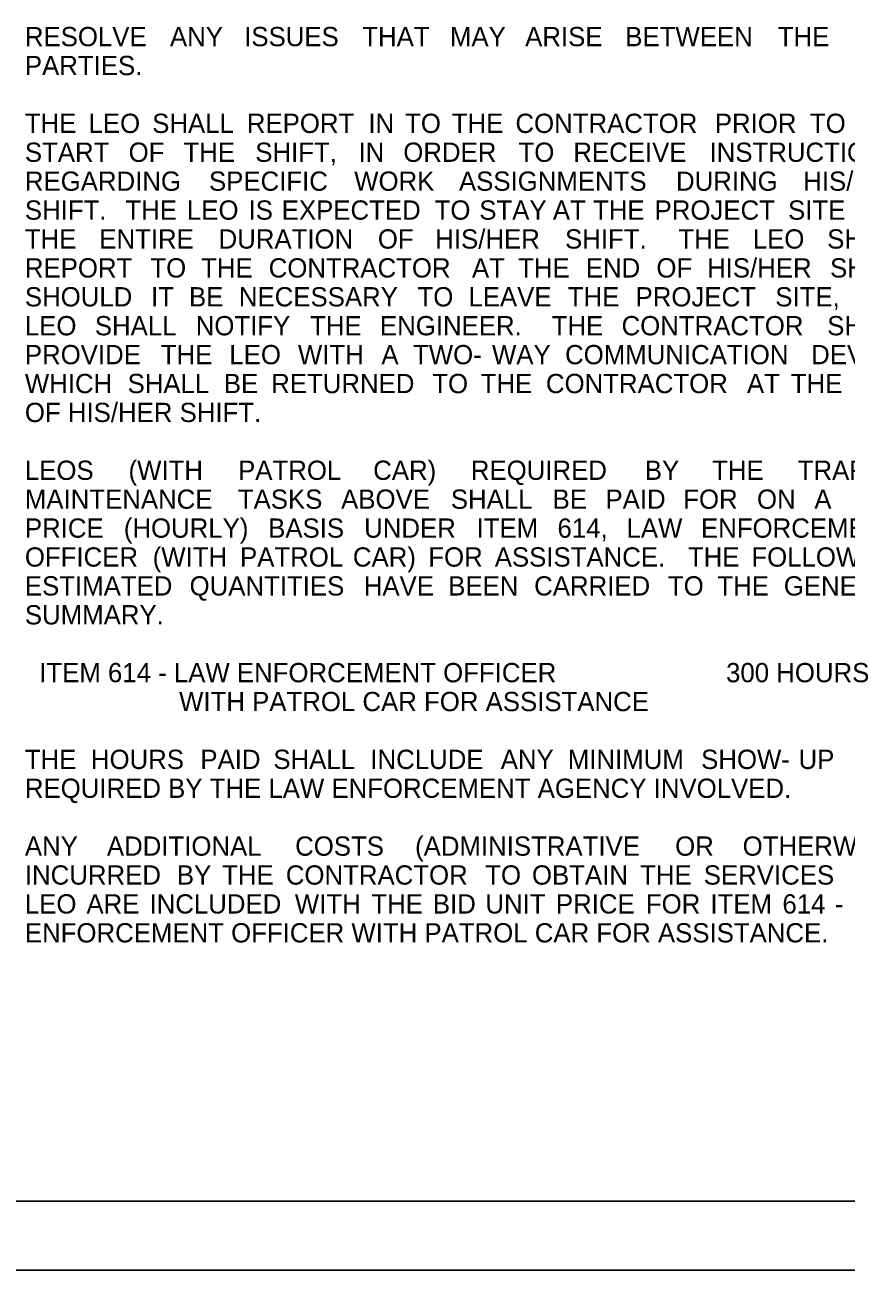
# Model space of a CAD drawing. Extents: x 0 to 34, y 0 to 22.
# Drawn here: x 24.66 to 30.62, y 0 to 9.04 of the extents above; entities that cross this region are included whole.
import ezdxf

# ---------------------------------------------------------------- set-up
doc = ezdxf.new("R2010")
doc.units = 0
for name, color, linetype in [('SH_Border', 7, 'Continuous'), ('SH_Cut_Line', 7, 'Continuous'), ('SH_Text', 7, 'Continuous')]:
    doc.layers.add(name, color=color, linetype=linetype)

msp = doc.modelspace()

# ---------------------------------------------------------------- linework, layer by layer
at = {"layer": 'SH_Border'}
msp.add_lwpolyline([(1.5, 21.5), (33.5, 21.5), (33.5, 0.5), (1.5, 0.5)], close=True, dxfattribs=at)
at = {"layer": 'SH_Cut_Line'}
msp.add_lwpolyline([(0, 0), (34, 0), (34, 22), (0, 22)], close=True, dxfattribs=at)

# ---------------------------------------------------------------- texts
at = {"layer": 'SH_Text'}
for s, p in [('RESOLVE ', (24.66, 8.89)), ('ANY ', (25.7136, 8.89)), ('ISSUES ', (26.2526, 8.89)), ('THAT ', (27.1103, 8.89)), ('MAY ', (27.7468, 8.89)), ('ARISE ', (28.2929, 8.89)), ('BETWEEN ', (29.0202, 8.89)), ('THE ', (30.1278, 8.89)), ('PARTIES.', (24.66, 8.68)), ('THE ', (24.66, 8.26)), ('LEO ', (25.1223, 8.26)), ('SHALL ', (25.5846, 8.26)), ('REPORT ', (26.2718, 8.26)), ('IN ', (27.1545, 8.26)), ('TO ', (27.4211, 8.26)), ('THE ', (27.7602, 8.26)), ('CONTRACTOR ', (28.2225, 8.26)), ('PRIOR ', (29.6702, 8.26)), ('TO ', (30.3607, 8.26)), ('START ', (24.66, 8.05)), ('OF ', (25.4134, 8.05)), ('THE ', (25.8116, 8.05)), ('SHIFT, ', (26.333, 8.05)), ('IN ', (27.0825, 8.05)), ('ORDER ', (27.4081, 8.05)), ('TO ', (28.2447, 8.05)), ('RECEIVE ', (28.643, 8.05)), ('INSTRUCTIONS ', (29.6319, 8.05)), ('REGARDING ', (24.66, 7.84)), ('SPECIFIC ', (25.997, 7.84)), ('WORK ', (27.0514, 7.84)), ('ASSIGNMENTS ', (27.8122, 7.84)), ('DURING ', (29.3885, 7.84)), ('HIS/HER ', (30.3123, 7.84)), ('SHIFT.  ', (24.66, 7.63)), ('THE ', (25.3897, 7.63)), ('LEO ', (25.837, 7.63)), ('IS ', (26.2843, 7.63)), ('EXPECTED ', (26.5251, 7.63)), ('TO ', (27.6357, 7.63)), ('STAY ', (27.9598, 7.63)), ('AT ', (28.4942, 7.63)), ('THE ', (28.7857, 7.63)), ('PROJECT ', (29.233, 7.63)), ('SITE ', (30.202, 7.63)), ('THE ', (24.66, 7.42)), ('ENTIRE ', (25.2004, 7.42)), ('DURATION ', (26.0668, 7.42)), ('OF ', (27.223, 7.42)), ('HIS/HER ', (27.6402, 7.42)), ('SHIFT.  ', (28.5828, 7.42)), ('THE ', (29.4056, 7.42)), ('LEO ', (29.946, 7.42)), ('SHALL ', (30.4864, 7.42)), ('REPORT ', (24.66, 7.21)), ('TO ', (25.5715, 7.21)), ('THE ', (25.9394, 7.21)), ('CONTRACTOR ', (26.4305, 7.21)), ('AT ', (27.9069, 7.21)), ('THE ', (28.2422, 7.21)), ('END ', (28.7333, 7.21)), ('OF ', (29.2461, 7.21)), ('HIS/HER ', (29.614, 7.21)), ('SHIFT. ', (30.5072, 7.21)), ('SHOULD ', (24.66, 7)), ('IT ', (25.5766, 7)), ('BE ', (25.8517, 7)), ('NECESSARY ', (26.2141, 7)), ('TO ', (27.5115, 7)), ('LEAVE ', (27.881, 7)), ('THE ', (28.6023, 7)), ('PROJECT ', (29.0949, 7)), ('SITE, ', (30.1094, 7)), ('LEO ', (24.66, 6.79)), ('SHALL ', (25.1679, 6.79)), ('NOTIFY ', (25.9006, 6.79)), ('THE ', (26.7308, 6.79)), ('ENGINEER.  ', (27.2386, 6.79)), ('THE ', (28.4855, 6.79)), ('CONTRACTOR ', (28.9932, 6.79)), ('SHALL ', (30.4864, 6.79)), ('PROVIDE ', (24.66, 6.58)), ('THE ', (25.647, 6.58)), ('LEO ', (26.1448, 6.58)), ('WITH ', (26.6427, 6.58)), ('A ', (27.2489, 6.58)), ('TWO-', (27.4787, 6.58)), ('WAY ', (28.0522, 6.58)), ('COMMUNICATION ', (28.5828, 6.58)), ('DEVICE ', (30.37, 6.58)), ('WHICH ', (24.66, 6.37)), ('SHALL ', (25.4057, 6.37)), ('BE ', (26.1048, 6.37)), ('RETURNED ', (26.4488, 6.37)), ('TO ', (27.6186, 6.37)), ('THE ', (27.9697, 6.37)), ('CONTRACTOR ', (28.4439, 6.37)), ('AT ', (29.9036, 6.37)), ('THE ', (30.222, 6.37)), ('OF HIS/HER SHIFT.', (24.66, 6.16)), ('LEOS ', (24.66, 5.74)), ('(WITH ', (25.4128, 5.74)), ('PATROL ', (26.2084, 5.74)), ('CAR) ', (27.1894, 5.74)), ('REQUIRED ', (27.8984, 5.74)), ('BY ', (29.1619, 5.74)), ('THE ', (29.6502, 5.74)), ('TRAFFIC ', (30.2724, 5.74)), ('MAINTENANCE ', (24.66, 5.53)), ('TASKS ', (26.2067, 5.53)), ('ABOVE ', (26.9564, 5.53)), ('SHALL ', (27.7533, 5.53)), ('BE ', (28.4923, 5.53)), ('PAID ', (28.8761, 5.53)), ('FOR ', (29.4409, 5.53)), ('ON ', (29.9766, 5.53)), ('A ', (30.3928, 5.53)), ('PRICE ', (24.66, 5.32)), ('(HOURLY) ', (25.3785, 5.32)), ('BASIS ', (26.4267, 5.32)), ('UNDER ', (27.1236, 5.32)), ('ITEM ', (27.9399, 5.32)), ('614, ', (28.5278, 5.32)), ('LAW ', (29.029, 5.32)), ('ENFORCEMENT ', (29.5699, 5.32)), ('OFFICER ', (24.66, 5.11)), ('(WITH ', (25.5881, 5.11)), ('PATROL ', (26.2224, 5.11)), ('CAR) ', (27.042, 5.11)), ('FOR ', (27.5897, 5.11)), ('ASSISTANCE.  ', (28.0721, 5.11)), ('THE ', (29.4751, 5.11)), ('FOLLOWING ', (29.9359, 5.11)), ('ESTIMATED ', (24.66, 4.9)), ('QUANTITIES ', (25.8561, 4.9)), ('HAVE ', (27.1211, 4.9)), ('BEEN ', (27.7342, 4.9)), ('CARRIED ', (28.3581, 4.9)), ('TO ', (29.3296, 4.9)), ('THE ', (29.6888, 4.9)), ('GENERAL ', (30.1712, 4.9)), ('SUMMARY.', (24.66, 4.69)), ('  ITEM 614 - LAW ENFORCEMENT OFFICER ', (24.66, 4.27)), (' 300 HOURS', (29.7, 4.27)), ('WITH PATROL CAR FOR ASSISTANCE', (25.78, 4.06)), ('THE ', (24.66, 3.64)), ('HOURS ', (25.1395, 3.64)), ('PAID ', (25.9342, 3.64)), ('SHALL ', (26.4645, 3.64)), ('INCLUDE ', (27.1689, 3.64)), ('ANY ', (28.1157, 3.64)), ('MINIMUM ', (28.6027, 3.64)), ('SHOW-', (29.5709, 3.64)), ('UP ', (30.2784, 3.64)), ('REQUIRED BY THE LAW ENFORCEMENT AGENCY INVOLVED.', (24.66, 3.43)), ('ANY ', (24.66, 3.01)), ('ADDITIONAL ', (25.2556, 3.01)), ('COSTS ', (26.6227, 3.01)), ('(ADMINISTRATIVE ', (27.4935, 3.01)), ('OR ', (29.3821, 3.01)), ('OTHERWISE) ', (29.8723, 3.01)), ('INCURRED ', (24.66, 2.8)), ('BY ', (25.7638, 2.8)), ('THE ', (26.0925, 2.8)), ('CONTRACTOR ', (26.5551, 2.8)), ('TO ', (28.003, 2.8)), ('OBTAIN ', (28.3425, 2.8)), ('THE ', (29.1275, 2.8)), ('SERVICES ', (29.59, 2.8)), ('LEO ', (24.66, 2.59)), ('ARE ', (25.107, 2.59)), ('INCLUDED ', (25.5649, 2.59)), ('WITH ', (26.6205, 2.59)), ('THE ', (27.1758, 2.59)), ('BID ', (27.6227, 2.59)), ('UNIT ', (28.0044, 2.59)), ('PRICE ', (28.5164, 2.59)), ('FOR ', (29.1698, 2.59)), ('ITEM ', (29.6384, 2.59)), ('614 ', (30.1613, 2.59)), ('- ', (30.5431, 2.59)), ('ENFORCEMENT OFFICER WITH PATROL CAR FOR ASSISTANCE.', (24.66, 2.38))]:
    msp.add_text(s, height=0.14, dxfattribs=at).set_placement(p)

doc.saveas('drawing.dxf')
